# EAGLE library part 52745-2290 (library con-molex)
FFC/FPC-to-Board 0.50mm (.020") SMT Top Contact Right Angle, ZIF, Style Receptacle 52745 / 52435 Source: http://www.molex.com/product/ffc/52745.html
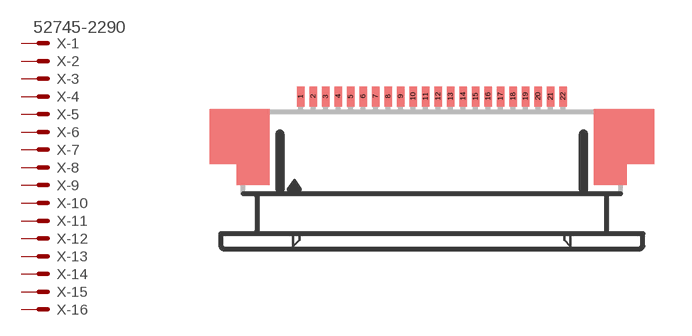
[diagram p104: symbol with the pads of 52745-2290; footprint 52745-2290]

Designator prefix X; gates -1=MV -2=M -3=M -4=M -5=M -6=M -7=M -8=M -9=M -10=M -11=M -12=M -13=M -14=M -15=M -16=M -17=M -18=M -19=M -20=M -21=M -22=M

## 52745-2290 (OC_FARNELL: unknown; OC_NEWARK: unknown)  [52745-2290]
1  -1:S  pas
2  -2:S  pas
3  -3:S  pas
4  -4:S  pas
5  -5:S  pas
6  -6:S  pas
7  -7:S  pas
8  -8:S  pas
9  -9:S  pas
10  -10:S  pas
11  -11:S  pas
12  -12:S  pas
13  -13:S  pas
14  -14:S  pas
15  -15:S  pas
16  -16:S  pas
17  -17:S  pas
18  -18:S  pas
19  -19:S  pas
20  -20:S  pas
21  -21:S  pas
22  -22:S  pas

## Footprint 52745-2290 (pad centres in mm)
FFC/FPC-to-Board 0.50mm (.020") SMT Top Contact Right Angle, ZIF, Style Receptacle 52745 / 52435 Source: http://www.molex.com/product/ffc/52745.html
smd 0.3 x 0.8: 1 -5.25,2.5; 2 -4.75,2.5; 3 -4.25,2.5; 4 -3.75,2.5; 5 -3.25,2.5; 6 -2.75,2.5; 7 -2.25,2.5; 8 -1.75,2.5; 9 -1.25,2.5; 10 -0.75,2.5; 11 -0.25,2.5; 12 0.25,2.5; 13 0.75,2.5; 14 1.25,2.5; 15 1.75,2.5; 16 2.25,2.5; 17 2.75,2.5; 18 3.25,2.5; 19 3.75,2.5; 20 4.25,2.5; 21 4.75,2.5; 22 5.25,2.5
